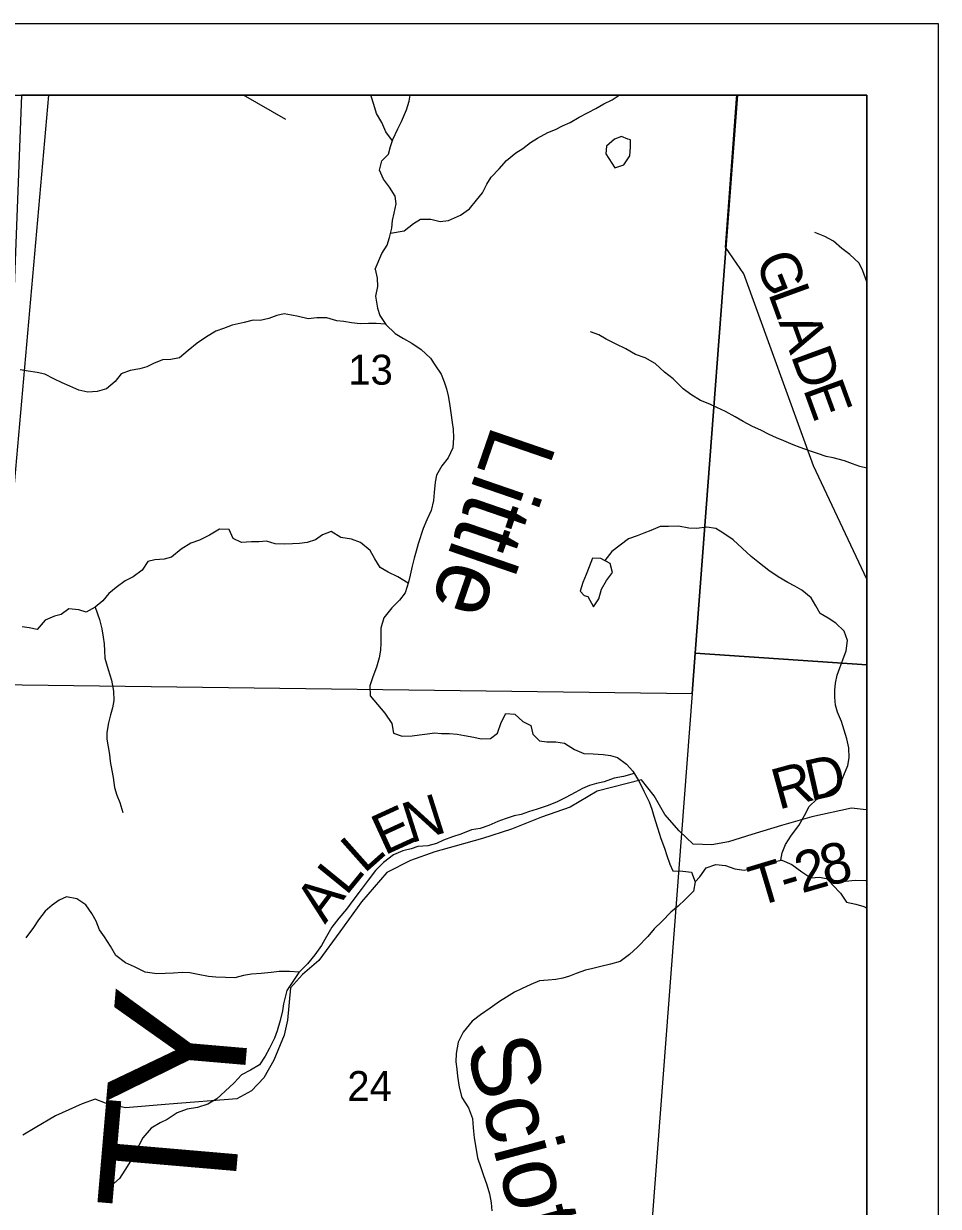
# Model space of a CAD drawing. Extents: x 0 to 40.8, y 0 to 22.
# Drawn here: x 7.723 to 9, y 19.348 to 21 of the extents above; entities that cross this region are included whole.
import ezdxf

# ---------------------------------------------------------------- set-up
doc = ezdxf.new("R2010")
doc.units = 0
for name, color, linetype in [('Default', 7, 'Continuous'), ('GM_X_County_Road', 7, 'Continuous'), ('GM_X_County_Road_Text', 7, 'Continuous'), ('GM_X_County_Text', 7, 'Continuous'), ('GM_X_Major_River', 7, 'Continuous'), ('GM_X_Major_River_Text', 7, 'Continuous'), ('GM_X_Minor_Lake', 7, 'Continuous'), ('GM_X_Minor_River', 7, 'Continuous'), ('GM_X_Section', 7, 'Continuous'), ('GM_X_Section_Text', 7, 'Continuous'), ('GM_X_Township_Road', 7, 'Continuous'), ('GM_X_Township_Road_Text', 7, 'Continuous'), ('SH_Cut_Line', 7, 'Continuous'), ('SH_Data', 7, 'Continuous')]:
    doc.layers.add(name, color=color, linetype=linetype)

msp = doc.modelspace()

# ---------------------------------------------------------------- linework, layer by layer
at = {"layer": 'Default'}
msp.add_lwpolyline([(8.9, 16.9831), (8.9, 20.9), (7.7204, 20.9), (7.7055, 20.511), (7.6192, 19.376), (7.6007, 19.1071), (7.6007, 19.1025), (7.595, 19.0259), (7.5789, 18.8336), (7.5246, 18.2047), (7.4963, 17.9476), (7.4798, 17.5479), (7.4495, 17.0841), (7.54, 17.0745), (7.7144, 17.066), (7.7161, 17.0658)], close=True, dxfattribs=at)
at = {"layer": 'GM_X_County_Road'}
for points in [[(8.7198, 20.9), (7.7581, 20.9), (7.6848, 20.077), (8.6564, 20.0646), (8.6604, 20.121)], [(8.9, 20.1045), (8.9, 20.9), (8.7198, 20.9), (8.6604, 20.121)], [(8.9, 19.0687), (8.9, 20.1045), (8.6604, 20.121), (8.6564, 20.0646), (8.5831, 19.0989)]]:
    msp.add_lwpolyline(points, close=True, dxfattribs=at)
msp.add_lwpolyline([(8.9, 20.224), (8.8259, 20.3825), (8.7287, 20.6506), (8.7028, 20.6879), (8.7182, 20.8952), (8.7186, 20.9)], dxfattribs=at)
at = {"layer": 'GM_X_Major_River'}
for points in [[(8.214, 20.6571), (8.2232, 20.6789), (8.2308, 20.6906), (8.2339, 20.7012), (8.2371, 20.7144), (8.2383, 20.7251), (8.2406, 20.7353), (8.243, 20.7485), (8.2416, 20.7592), (8.2341, 20.7717), (8.2255, 20.7828), (8.2199, 20.7953), (8.223, 20.8086), (8.2326, 20.8176), (8.2353, 20.8282), (8.2384, 20.838), (8.2457, 20.8532), (8.2507, 20.8634), (8.2576, 20.8796), (8.2615, 20.8917), (8.2628, 20.9)], [(8.214, 20.6571), (8.2166, 20.6446), (8.2172, 20.6328), (8.2145, 20.6196), (8.2174, 20.6028), (8.2203, 20.5926), (8.2289, 20.5796), (8.2417, 20.5674), (8.2533, 20.5601), (8.265, 20.5539), (8.2782, 20.5451), (8.2913, 20.5328), (8.2981, 20.5221), (8.3059, 20.5103), (8.3104, 20.4997), (8.3137, 20.4902), (8.3159, 20.4803), (8.3177, 20.4696), (8.3195, 20.4563), (8.3216, 20.4431), (8.3227, 20.4336), (8.3234, 20.4214), (8.3221, 20.4074), (8.3159, 20.3938), (8.3071, 20.3825), (8.2994, 20.3693), (8.2975, 20.3594), (8.2962, 20.3454), (8.2954, 20.334), (8.2922, 20.32), (8.2861, 20.3068), (8.281, 20.2947), (8.2741, 20.2735), (8.2713, 20.2633), (8.2682, 20.2535), (8.2655, 20.2425), (8.2627, 20.2296), (8.2604, 20.2198), (8.2557, 20.205), (8.2477, 20.1949), (8.237, 20.1839), (8.2259, 20.17), (8.222, 20.1556), (8.2219, 20.1446), (8.2218, 20.1351), (8.2213, 20.1249), (8.2194, 20.1143), (8.2158, 20.1011), (8.2108, 20.0878), (8.2065, 20.0753), (8.2068, 20.0613), (8.2173, 20.0491), (8.2274, 20.0369), (8.2371, 20.0224), (8.2393, 20.0091), (8.2514, 20.0048), (8.2654, 20.0054), (8.276, 20.0069), (8.287, 20.0083), (8.2965, 20.0094), (8.3067, 20.0085), (8.3177, 20.0084), (8.3286, 20.0076), (8.3385, 20.006), (8.3517, 20.0036), (8.3619, 20.0012), (8.3748, 20.0015), (8.3847, 20.009), (8.3897, 20.0238), (8.3962, 20.0366), (8.4087, 20.0357), (8.42, 20.0254), (8.4313, 20.02), (8.4342, 20.0078), (8.4432, 19.9983), (8.4534, 19.9971), (8.4659, 19.9969), (8.4784, 19.9953), (8.4923, 19.9861), (8.5052, 19.9807), (8.518, 19.9802), (8.532, 19.9793), (8.5426, 19.9781), (8.5524, 19.975), (8.5649, 19.9658), (8.5735, 19.9562), (8.5824, 19.9414), (8.5891, 19.928), (8.5962, 19.9132), (8.5999, 19.9029), (8.6029, 19.893), (8.608, 19.877), (8.6128, 19.8618), (8.6176, 19.8485), (8.621, 19.8383), (8.625, 19.8261), (8.6295, 19.8166), (8.6435, 19.8164), (8.6556, 19.8148), (8.6608, 19.8015), (8.6584, 19.7883)], [(8.6584, 19.7883), (8.6466, 19.7766), (8.637, 19.7676), (8.6264, 19.7593), (8.6145, 19.7465), (8.6034, 19.7356), (8.5943, 19.7251), (8.5801, 19.7104), (8.5687, 19.6999), (8.5558, 19.6901), (8.5425, 19.6864), (8.5288, 19.6831), (8.5178, 19.6802), (8.5076, 19.678), (8.4947, 19.6735), (8.4852, 19.6698), (8.4757, 19.6669), (8.4662, 19.6651), (8.4556, 19.664), (8.4435, 19.663), (8.431, 19.6581), (8.4184, 19.6522), (8.4082, 19.6473), (8.3971, 19.6402), (8.3876, 19.6342), (8.3743, 19.6252), (8.361, 19.6159), (8.3491, 19.6069), (8.3369, 19.5914), (8.3296, 19.5774), (8.3268, 19.5615), (8.3267, 19.5502), (8.3278, 19.5399), (8.3288, 19.53), (8.3313, 19.5145), (8.335, 19.5004), (8.344, 19.4859), (8.3499, 19.4711), (8.3509, 19.4578), (8.3523, 19.4441), (8.3548, 19.4274), (8.3566, 19.416), (8.3615, 19.4023), (8.3648, 19.3928), (8.37, 19.3784), (8.3736, 19.3658), (8.3758, 19.3529), (8.3769, 19.3419)]]:
    msp.add_lwpolyline(points, dxfattribs=at)
at = {"layer": 'GM_X_Minor_Lake'}
for points in [[(8.5667, 20.8389), (8.5576, 20.8422), (8.5478, 20.8388), (8.5367, 20.8287), (8.5359, 20.8181), (8.5486, 20.7987)], [(8.5486, 20.7987), (8.5608, 20.8027), (8.5692, 20.8156), (8.5704, 20.8273), (8.5705, 20.8376), (8.5667, 20.8389)], [(8.545, 20.2333), (8.542, 20.2462), (8.5291, 20.2531), (8.5173, 20.2534), (8.5124, 20.2413), (8.5082, 20.2307), (8.5037, 20.2197), (8.4999, 20.2075), (8.5055, 20.2015)], [(8.5055, 20.2015), (8.5106, 20.2001), (8.5188, 20.1855), (8.526, 20.1965), (8.5298, 20.2102), (8.537, 20.2223), (8.545, 20.2333)]]:
    msp.add_lwpolyline(points, dxfattribs=at)
at = {"layer": 'GM_X_Minor_River'}
msp.add_line((8.9, 20.6395), (8.8945, 20.6547), dxfattribs=at)
for points in [[(8.2379, 20.8365), (8.229, 20.8489), (8.2234, 20.8618), (8.2159, 20.8744), (8.2119, 20.8873), (8.2085, 20.8987), (8.2078, 20.9)], [(8.2354, 20.7074), (8.2542, 20.7108), (8.2675, 20.7209), (8.2774, 20.7269), (8.2914, 20.7268), (8.3046, 20.7237), (8.3163, 20.7251), (8.333, 20.7326), (8.3456, 20.7416), (8.3555, 20.7537), (8.3639, 20.7639), (8.37, 20.776), (8.3757, 20.7858), (8.3871, 20.7971), (8.3974, 20.8091), (8.4104, 20.8197), (8.4202, 20.8257), (8.4305, 20.8339), (8.4404, 20.8403), (8.4548, 20.8478), (8.4658, 20.8523), (8.4753, 20.8571), (8.4859, 20.862), (8.4988, 20.8695), (8.5113, 20.8758), (8.522, 20.8815), (8.533, 20.8878), (8.5447, 20.8934), (8.5547, 20.9)], [(8.8945, 20.6547), (8.8893, 20.6657), (8.8765, 20.6775), (8.8652, 20.6859), (8.8536, 20.6962), (8.8415, 20.7027), (8.8276, 20.7085)], [(8.2284, 20.5803), (8.2152, 20.5811), (8.2046, 20.5811), (8.1929, 20.5808), (8.1808, 20.5823), (8.1702, 20.5839), (8.1603, 20.5851), (8.1463, 20.5893), (8.1327, 20.589), (8.1202, 20.5879), (8.107, 20.5909), (8.0971, 20.5929), (8.0869, 20.5948), (8.0767, 20.5922), (8.0653, 20.588), (8.0536, 20.5854), (8.0437, 20.5858), (8.0312, 20.5825), (8.0142, 20.5787), (8.0021, 20.5742), (7.9915, 20.5705), (7.9786, 20.5626), (7.9653, 20.5539), (7.9531, 20.5433), (7.941, 20.5335), (7.9289, 20.5309), (7.9171, 20.5305), (7.9046, 20.5253), (7.8952, 20.5208), (7.8853, 20.5178), (7.8717, 20.5155), (7.8592, 20.511), (7.8512, 20.5004), (7.839, 20.4899), (7.8258, 20.4861), (7.8129, 20.4854), (7.8004, 20.4881), (7.7879, 20.4938), (7.777, 20.4984), (7.7656, 20.5041), (7.7528, 20.5103), (7.7422, 20.5126), (7.7297, 20.5145), (7.7183, 20.5166)], [(8.9, 20.3792), (8.8905, 20.3816), (8.8803, 20.3854), (8.8689, 20.3892), (8.8534, 20.3938), (8.8436, 20.3954), (8.8315, 20.3996), (8.8201, 20.4034), (8.8073, 20.408), (8.7975, 20.4118), (8.7842, 20.4172), (8.774, 20.4214), (8.7638, 20.426), (8.7521, 20.4321), (8.7408, 20.4374), (8.7276, 20.4443), (8.7166, 20.4508), (8.703, 20.4584), (8.6909, 20.4638), (8.6811, 20.4684), (8.6679, 20.4737), (8.6546, 20.4821), (8.6437, 20.4901), (8.6297, 20.5038), (8.618, 20.5133), (8.6048, 20.5255), (8.5909, 20.5335), (8.5773, 20.5381), (8.5637, 20.5457), (8.5501, 20.5522), (8.5365, 20.5595), (8.5263, 20.5652), (8.5145, 20.5694)], [(8.26, 20.2186), (8.2454, 20.2276), (8.2321, 20.2337), (8.2208, 20.2406), (8.2136, 20.2527), (8.2069, 20.2641), (8.1933, 20.2752), (8.1808, 20.2801), (8.1661, 20.2825), (8.1525, 20.2905), (8.1403, 20.286), (8.1305, 20.2792), (8.1191, 20.2754), (8.1081, 20.274), (8.0983, 20.2736), (8.0877, 20.2729), (8.0744, 20.2737), (8.062, 20.2771), (8.0521, 20.2764), (8.0415, 20.2761), (8.0275, 20.2754), (8.0158, 20.2811), (8.0102, 20.2936), (7.9965, 20.2941), (7.9825, 20.2858), (7.9685, 20.2786), (7.9567, 20.2745), (7.9431, 20.2662), (7.9298, 20.2549), (7.9196, 20.2522), (7.9063, 20.2511), (7.8965, 20.2489), (7.8885, 20.2368), (7.8763, 20.2274), (7.8649, 20.2217), (7.8524, 20.2123), (7.8422, 20.204), (7.8338, 20.1938), (7.8232, 20.1851), (7.8103, 20.1779), (7.8005, 20.1814), (7.7861, 20.1829), (7.7758, 20.1746), (7.7664, 20.1724), (7.7531, 20.1667), (7.7421, 20.1539), (7.7311, 20.1562), (7.7213, 20.1574)], [(8.7802, 19.8315), (8.7818, 19.842), (8.7868, 19.8534), (8.7952, 19.8666), (8.8054, 19.8799), (8.8134, 19.8939), (8.8199, 19.9067), (8.8305, 19.9169), (8.8434, 19.9252), (8.8533, 19.9313), (8.8639, 19.9403), (8.8681, 19.9502), (8.8735, 19.9638), (8.8754, 19.9744), (8.8751, 19.9888), (8.8721, 20.0013), (8.8687, 20.0131), (8.865, 20.0252), (8.8594, 20.0385), (8.8564, 20.0484), (8.8553, 20.0594), (8.8557, 20.0689), (8.8565, 20.0787), (8.8588, 20.0901), (8.8626, 20.1003), (8.8668, 20.1113), (8.8714, 20.1242), (8.873, 20.1386), (8.8685, 20.1515), (8.8568, 20.1629), (8.8462, 20.1698), (8.8349, 20.1763), (8.8292, 20.1869), (8.8224, 20.1979), (8.8096, 20.2086), (8.7998, 20.2143), (8.79, 20.2196), (8.7764, 20.2273), (8.7632, 20.2364), (8.7503, 20.2467), (8.7386, 20.2558), (8.7262, 20.2676), (8.7137, 20.2791), (8.6994, 20.289), (8.6896, 20.2947), (8.6767, 20.2966), (8.6623, 20.2948), (8.6517, 20.2956), (8.6373, 20.2983), (8.6233, 20.2976), (8.6116, 20.2976), (8.5987, 20.2923), (8.5889, 20.2882), (8.5794, 20.2845), (8.5676, 20.2803), (8.5559, 20.2716), (8.5441, 20.2626), (8.5346, 20.2501)], [(7.8229, 20.1849), (7.8292, 20.1676), (7.8322, 20.1547), (7.8344, 20.1433), (7.8355, 20.1338), (7.8362, 20.124), (7.8366, 20.1137), (7.8414, 20.0978), (7.8459, 20.083), (7.8485, 20.0678), (7.8492, 20.0549), (7.8473, 20.0443), (7.8446, 20.0345), (7.8419, 20.0235), (7.8392, 20.0102), (7.8392, 20.0007), (7.8429, 19.9795), (7.844, 19.9696), (7.8462, 19.9571), (7.8481, 19.9473), (7.8499, 19.9332), (7.8533, 19.9226), (7.8574, 19.9123), (7.8615, 19.8983)], [(8.5755, 19.9529), (8.5604, 19.9486), (8.5475, 19.9463), (8.5335, 19.9411), (8.5229, 19.9389), (8.513, 19.9359), (8.5032, 19.9317), (8.4933, 19.9264), (8.4801, 19.9193), (8.4668, 19.9125), (8.4539, 19.9076), (8.4399, 19.9031), (8.4281, 19.8994), (8.4179, 19.8956), (8.4077, 19.8934), (8.3952, 19.8892), (8.3853, 19.8855), (8.3728, 19.8802), (8.3607, 19.8761), (8.3482, 19.8739), (8.3334, 19.8678), (8.322, 19.8645), (8.3095, 19.8596), (8.2993, 19.8551), (8.2875, 19.8517), (8.2735, 19.8506), (8.2641, 19.8476), (8.2523, 19.8446), (8.2394, 19.839), (8.2254, 19.8284), (8.2144, 19.8175), (8.2041, 19.8038), (8.1946, 19.7906), (8.1843, 19.7774), (8.1737, 19.7634), (8.1634, 19.7505), (8.1535, 19.738), (8.1459, 19.7252), (8.1391, 19.7123), (8.1296, 19.6994), (8.1193, 19.687), (8.1075, 19.6749), (8.0988, 19.6624), (8.0904, 19.6499), (8.0881, 19.6404), (8.0858, 19.631), (8.0846, 19.6211), (8.0812, 19.6079), (8.0769, 19.5935), (8.0735, 19.5832), (8.0666, 19.5692), (8.0605, 19.5579), (8.0526, 19.5458), (8.0397, 19.5382), (8.0275, 19.5318), (8.0173, 19.5209), (8.0047, 19.5092), (7.993, 19.4986), (7.9804, 19.491), (7.9657, 19.4862), (7.9517, 19.4839), (7.9376, 19.4787), (7.9236, 19.4696), (7.9137, 19.4647), (7.9012, 19.4572), (7.8898, 19.444), (7.8841, 19.4334), (7.8772, 19.4212), (7.8723, 19.4114), (7.8643, 19.3989), (7.8571, 19.3872), (7.8449, 19.3762)], [(8.6608, 19.8015), (8.667, 19.8083), (8.6761, 19.8208), (8.6894, 19.8257), (8.7027, 19.8241), (8.7159, 19.8195), (8.7291, 19.8176), (8.7416, 19.8205), (8.7553, 19.8254), (8.7685, 19.8292), (8.7814, 19.8318), (8.7954, 19.8257), (8.8094, 19.8154), (8.8218, 19.807), (8.8343, 19.8081), (8.8483, 19.805), (8.8604, 19.8023), (8.8703, 19.8023), (8.8839, 19.8037), (8.899, 19.8033), (8.9, 19.8032)], [(8.8449, 19.8058), (8.8528, 19.7967), (8.8634, 19.7856), (8.872, 19.7731), (8.8849, 19.7704), (8.8962, 19.7669), (8.9, 19.7645)], [(8.1077, 19.6751), (8.0943, 19.6764), (8.0799, 19.6761), (8.0689, 19.6746), (8.0549, 19.6735), (8.0413, 19.6725), (8.0303, 19.6706), (8.0178, 19.6672), (8.0049, 19.668), (7.9913, 19.6681), (7.9811, 19.6692), (7.9667, 19.6719), (7.955, 19.6743), (7.9451, 19.6747), (7.9323, 19.674), (7.9209, 19.6736), (7.9092, 19.6729), (7.8929, 19.6752), (7.8782, 19.6829), (7.8653, 19.6882), (7.8521, 19.6985), (7.8446, 19.7118), (7.8363, 19.7247), (7.8292, 19.7346), (7.8243, 19.7464), (7.8183, 19.7574), (7.81, 19.7692), (7.7975, 19.7779), (7.7831, 19.7803), (7.7729, 19.7757), (7.763, 19.769), (7.7535, 19.7603), (7.744, 19.7482), (7.7372, 19.7376), (7.7262, 19.7232)]]:
    msp.add_lwpolyline(points, dxfattribs=at)
at = {"layer": 'GM_X_Section'}
msp.add_lwpolyline([(7.6848, 20.077), (8.6564, 20.0646), (8.5831, 19.0989), (8.5731, 18.9686), (7.596, 19.0268)], close=True, dxfattribs=at)
at = {"layer": 'GM_X_Township_Road'}
msp.add_line((8.0893, 20.8663), (8.0302, 20.9), dxfattribs=at)
msp.add_lwpolyline([(8.9, 19.902), (8.8994, 19.9019), (8.8786, 19.9042), (8.8232, 19.8923), (8.7812, 19.88), (8.7395, 19.8674), (8.7073, 19.8571), (8.6838, 19.8529), (8.658, 19.8539), (8.6382, 19.8725), (8.6181, 19.8956), (8.6032, 19.9217), (8.5858, 19.9437), (8.5236, 19.928), (8.4861, 19.9055), (8.446, 19.8918), (8.4043, 19.875), (8.3637, 19.862), (8.3255, 19.8513), (8.2974, 19.8432), (8.2633, 19.8314), (8.2304, 19.8146), (8.1948, 19.7736), (8.1646, 19.7318), (8.1355, 19.6915), (8.1124, 19.6721), (8.0957, 19.6535), (8.0916, 19.6083), (8.0868, 19.5875), (8.0724, 19.5525), (8.0585, 19.5278), (8.0414, 19.5096), (8.021, 19.4982), (7.9262, 19.4911), (7.8652, 19.486), (7.8375, 19.4924), (7.8231, 19.4977), (7.8049, 19.4912), (7.7677, 19.4748), (7.7393, 19.458), (7.7219, 19.4474)], dxfattribs=at)
at = {"layer": 'SH_Cut_Line'}
msp.add_lwpolyline([(8.9, 16.9831), (8.9, 20.9), (7.7204, 20.9), (7.7055, 20.511), (7.6192, 19.376), (7.6007, 19.1071), (7.6007, 19.1025), (7.595, 19.0259), (7.5789, 18.8336), (7.5246, 18.2047), (7.4963, 17.9476), (7.4798, 17.5479), (7.4495, 17.0841), (7.54, 17.0745), (7.7144, 17.066), (7.7161, 17.0658)], close=True, dxfattribs=at)
at = {"layer": 'SH_Data'}
for p, q in [((2, 21), (9, 21)), ((9, 21), (9, 14)), ((2.1, 20.9), (8.9, 20.9)), ((8.9, 20.9), (8.9, 14.1))]:
    msp.add_line(p, q, dxfattribs=at)

# ---------------------------------------------------------------- texts
at = {"layer": 'GM_X_County_Road_Text'}
for s, rotation, p in [('G', 291.9218, (8.7436, 20.6695)), ('L', 290.0384, (8.762, 20.6236)), ('A', 290.018, (8.7766, 20.5837)), ('D', 290.0198, (8.7937, 20.5367)), ('E', 290.0186, (8.8108, 20.4897))]:
    msp.add_text(s, height=0.0568, rotation=rotation, dxfattribs=at).set_placement(p)
at = {"layer": 'GM_X_County_Text'}
for s, p in [('Y', (8.0266, 19.4734)), ('T', (8.0145, 19.3322))]:
    msp.add_text(s, height=0.1894, rotation=85.0789, dxfattribs=at).set_placement(p)
at = {"layer": 'GM_X_Major_River_Text'}
for s, rotation, p in [('Little', 251.0025, (8.378, 20.4422)), ('Scioto', 284.9983, (8.3398, 19.573))]:
    msp.add_text(s, height=0.09471, rotation=rotation, dxfattribs=at).set_placement(p)
at = {"layer": 'GM_X_Section_Text'}
for s, p in [('13', (8.1763, 20.4958)), ('24', (8.175, 19.4953))]:
    msp.add_text(s, height=0.04186, rotation=0, dxfattribs=at).set_placement(p)
at = {"layer": 'GM_X_Township_Road_Text'}
for s, rotation, p in [('D', 12.6967, (8.8213, 19.9141)), ('R', 15.3578, (8.7769, 19.9019)), ('N', 17.5813, (8.2635, 19.855)), ('E', 24.6596, (8.2267, 19.8379)), ('L', 41.604, (8.1986, 19.8121)), ('8', 13.2575, (8.8423, 19.7948)), ('2', 16.1205, (8.8094, 19.7852)), ('L', 50.9045, (8.1735, 19.7809)), ('T', 16.6512, (8.7464, 19.7664)), ('-', 16.5587, (8.7871, 19.7786)), ('A', 53.1753, (8.1439, 19.7414))]:
    msp.add_text(s, height=0.0568, rotation=rotation, dxfattribs=at).set_placement(p)

doc.saveas('drawing.dxf')
